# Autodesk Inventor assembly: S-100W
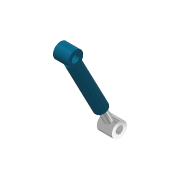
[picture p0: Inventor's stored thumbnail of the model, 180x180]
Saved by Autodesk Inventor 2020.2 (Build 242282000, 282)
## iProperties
Created: 2014-01
Part Number: S-100W
Document SubType Name: Assembly
Designer: F.Stasiak
Manager: www.cadconsulting.pl
Company: Fabian Stasiak CAD Consulting
Author: F.Stasiak
Subject: Zbiór ćwiczeń. Autodesk Inventor 2020. Kurs podstawowy
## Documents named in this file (3)
- C:\2020_Kurs_podstawowy\R6 Zespoły\Warsztat\Komponenty\S-100P.iam
- C:\2020_Kurs_podstawowy\R6 Zespoły\Warsztat\Komponenty\S-100.ipt
- C:\2020_Kurs_podstawowy\R6 Zespoły\Warsztat\Komponenty\S-101.ipt
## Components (2 placed, 2 different names)
1. S-100:1 — NAPĘD
2. S-101:1 — NAPĘD
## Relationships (1: Mate 1)
- NAPĘD [Mate]: S-100:1 ↔ S-101:1
